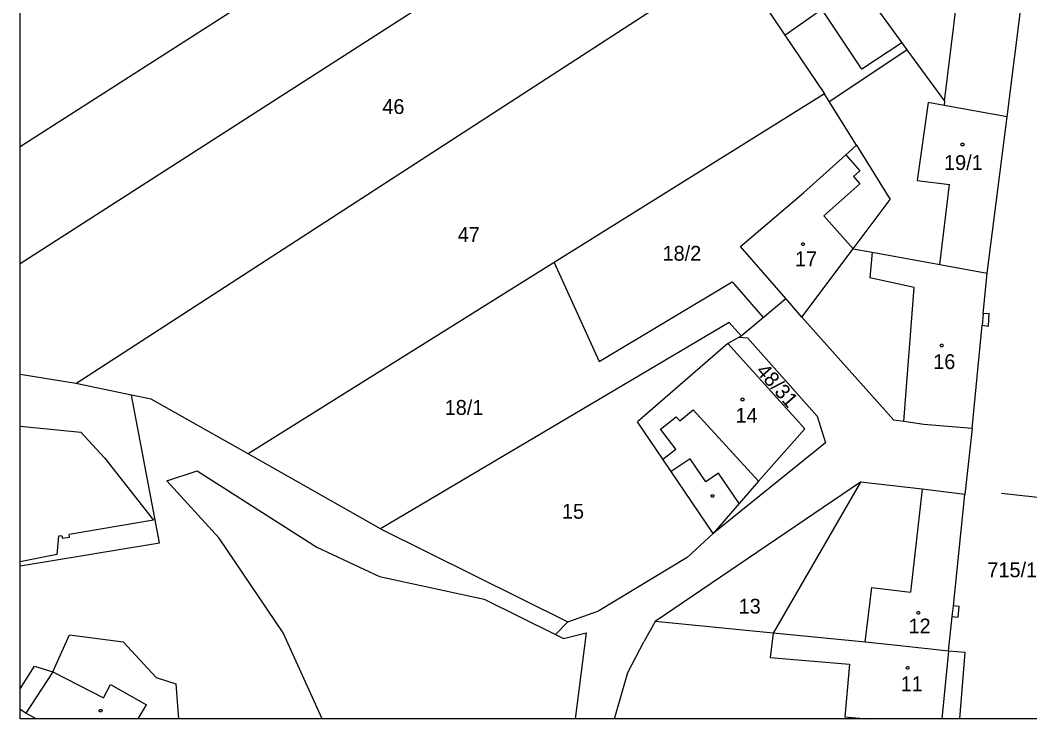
# Model space of a CAD drawing. Extents: x -639621 to -639329, y -1192893 to -1192488.
# Drawn here: x -639621.3 to -639505.7, y -1192893.3 to -1192813.4 of the extents above; entities that cross this region are included whole.
import ezdxf

# ---------------------------------------------------------------- set-up
doc = ezdxf.new("R2010")
doc.units = 0
for name, color, linetype in [('Vrstva 1', 7, 'Continuous'), ('Vrstva 2', 7, 'Continuous'), ('Vrstva 25', 7, 'Continuous'), ('Vrstva 4', 7, 'Continuous'), ('Vrstva 5', 7, 'Continuous'), ('Vrstva 61', 7, 'Continuous')]:
    doc.layers.add(name, color=color, linetype=linetype)

msp = doc.modelspace()

# ---------------------------------------------------------------- linework, layer by layer
at = {"layer": 'Vrstva 1'}
for p, q in [((-639544.66, -1192778.72), (-639621.26, -1192827.88)), ((-639621.26, -1192841.23), (-639539.3, -1192788.57)), ((-639531.35, -1192800.82), (-639520.33, -1192815.94)), ((-639508.25, -1192824.43), (-639505.7, -1192803.94)), ((-639614.88, -1192854.94), (-639539.7, -1192806.21)), ((-639539.7, -1192806.21), (-639533.72, -1192815.06)), ((-639533.72, -1192815.06), (-639529.19, -1192821.78)), ((-639520.33, -1192815.94), (-639519.74, -1192816.75)), ((-639528.63, -1192822.67), (-639519.74, -1192816.75)), ((-639519.74, -1192816.75), (-639515.43, -1192822.65)), ((-639529.19, -1192821.78), (-639560.12, -1192841.09)), ((-639528.63, -1192822.67), (-639529.19, -1192821.78)), ((-639525.5, -1192827.68), (-639528.63, -1192822.67)), ((-639515.43, -1192822.65), (-639515.49, -1192823.12)), ((-639508.25, -1192824.43), (-639515.49, -1192823.12)), ((-639510.56, -1192842.33), (-639508.25, -1192824.43)), ((-639526.73, -1192828.78), (-639525.5, -1192827.68)), ((-639525.5, -1192827.68), (-639521.67, -1192833.89)), ((-639531.59, -1192833.11), (-639526.73, -1192828.78)), ((-639538.8, -1192839.27), (-639531.59, -1192833.11)), ((-639525.91, -1192839.52), (-639521.67, -1192833.89)), ((-639533.62, -1192845.24), (-639538.8, -1192839.27)), ((-639531.79, -1192847.35), (-639525.91, -1192839.52)), ((-639525.91, -1192839.52), (-639523.71, -1192839.92)), ((-639523.71, -1192839.92), (-639515.97, -1192841.34)), ((-639560.12, -1192841.09), (-639595.18, -1192863)), ((-639560.12, -1192841.09), (-639554.98, -1192852.45)), ((-639515.97, -1192841.34), (-639510.56, -1192842.33)), ((-639511.01, -1192846.96), (-639510.56, -1192842.33)), ((-639554.98, -1192852.45), (-639539.77, -1192843.3)), ((-639539.77, -1192843.3), (-639536.21, -1192847.4)), ((-639536.21, -1192847.4), (-639533.62, -1192845.24)), ((-639531.79, -1192847.35), (-639533.62, -1192845.24)), ((-639510.32, -1192846.92), (-639511.01, -1192846.96)), ((-639510.42, -1192848.39), (-639510.32, -1192846.92)), ((-639540.09, -1192847.96), (-639580, -1192871.57)), ((-639538.71, -1192849.49), (-639540.09, -1192847.96)), ((-639538.71, -1192849.49), (-639536.21, -1192847.4)), ((-639521.25, -1192859.13), (-639531.79, -1192847.35)), ((-639512.29, -1192860.12), (-639511.14, -1192848.29)), ((-639511.14, -1192848.29), (-639510.42, -1192848.39)), ((-639540.23, -1192850.37), (-639550.59, -1192859.35)), ((-639540.23, -1192850.37), (-639538.98, -1192849.64)), ((-639531.42, -1192860.16), (-639540.23, -1192850.37)), ((-639538.98, -1192849.64), (-639538.71, -1192849.49)), ((-639538.98, -1192849.64), (-639538.01, -1192849.73)), ((-639538.01, -1192849.73), (-639530.02, -1192858.69)), ((-639614.88, -1192854.94), (-639621.26, -1192853.92)), ((-639608.52, -1192856.27), (-639614.88, -1192854.94)), ((-639605.31, -1192873.2), (-639608.52, -1192856.27)), ((-639606.26, -1192856.74), (-639608.52, -1192856.27)), ((-639595.18, -1192863), (-639606.26, -1192856.74)), ((-639530.02, -1192858.69), (-639529.06, -1192861.73)), ((-639621.26, -1192859.82), (-639614.31, -1192860.51)), ((-639547.69, -1192863.63), (-639550.59, -1192859.35)), ((-639520.08, -1192859.32), (-639521.25, -1192859.13)), ((-639517.82, -1192859.63), (-639520.08, -1192859.32)), ((-639512.29, -1192860.12), (-639517.82, -1192859.63)), ((-639614.31, -1192860.51), (-639611.62, -1192863.46)), ((-639531.42, -1192860.16), (-639536.75, -1192866.15)), ((-639512.29, -1192860.12), (-639513.1, -1192867.65)), ((-639529.06, -1192861.73), (-639541.93, -1192872.12)), ((-639580, -1192871.57), (-639595.18, -1192863)), ((-639611.62, -1192863.46), (-639606, -1192870.58)), ((-639546.73, -1192865.04), (-639547.69, -1192863.63)), ((-639604.47, -1192866.09), (-639601, -1192864.96)), ((-639601, -1192864.96), (-639587.31, -1192873.7)), ((-639541.93, -1192872.12), (-639546.73, -1192865.04)), ((-639598.5, -1192872.64), (-639604.47, -1192866.09)), ((-639525.06, -1192866.23), (-639548.56, -1192882.19)), ((-639536.75, -1192866.15), (-639538.95, -1192868.69)), ((-639525.06, -1192866.23), (-639535.07, -1192883.53)), ((-639517.99, -1192867.05), (-639525.06, -1192866.23)), ((-639513.1, -1192867.65), (-639517.99, -1192867.05)), ((-639514.43, -1192880.41), (-639513.1, -1192867.65)), ((-639538.95, -1192868.69), (-639541.93, -1192872.12)), ((-639606, -1192870.58), (-639615.65, -1192872.22)), ((-639616.87, -1192872.43), (-639617.06, -1192874.51)), ((-639616.49, -1192872.37), (-639616.87, -1192872.43)), ((-639616.49, -1192872.37), (-639616.43, -1192872.67)), ((-639616.43, -1192872.67), (-639615.6, -1192872.53)), ((-639615.6, -1192872.53), (-639615.65, -1192872.22)), ((-639580, -1192871.57), (-639558.56, -1192882.23)), ((-639541.93, -1192872.12), (-639544.9, -1192874.86)), ((-639621.26, -1192875.84), (-639605.31, -1192873.2)), ((-639591.17, -1192883.51), (-639598.5, -1192872.64)), ((-639587.31, -1192873.7), (-639580.13, -1192877.06)), ((-639617.06, -1192874.51), (-639621.26, -1192875.37)), ((-639544.9, -1192874.86), (-639555, -1192880.97)), ((-639580.13, -1192877.06), (-639568.16, -1192879.64)), ((-639568.16, -1192879.64), (-639559.97, -1192883.7)), ((-639513.76, -1192880.48), (-639514.43, -1192880.41)), ((-639513.89, -1192881.71), (-639513.76, -1192880.48)), ((-639558.56, -1192882.23), (-639555, -1192880.97)), ((-639514.97, -1192885.59), (-639514.56, -1192881.64)), ((-639514.56, -1192881.64), (-639513.89, -1192881.71)), ((-639559.97, -1192883.7), (-639558.56, -1192882.23)), ((-639548.56, -1192882.19), (-639549.88, -1192884.53)), ((-639535.07, -1192883.53), (-639548.56, -1192882.19)), ((-639617.51, -1192887.95), (-639615.62, -1192883.72)), ((-639615.62, -1192883.72), (-639609.46, -1192884.51)), ((-639586.7, -1192893.33), (-639591.17, -1192883.51)), ((-639559.97, -1192883.7), (-639559.07, -1192884.15)), ((-639559.07, -1192884.15), (-639556.45, -1192883.48)), ((-639556.45, -1192883.48), (-639557.71, -1192893.33)), ((-639526.07, -1192884.42), (-639535.07, -1192883.53)), ((-639609.46, -1192884.51), (-639605.69, -1192888.6)), ((-639551.68, -1192888.03), (-639549.88, -1192884.53)), ((-639524.51, -1192884.57), (-639526.07, -1192884.42)), ((-639520.5, -1192884.97), (-639524.51, -1192884.57)), ((-639514.97, -1192885.59), (-639520.5, -1192884.97)), ((-639513.07, -1192885.76), (-639514.97, -1192885.59)), ((-639513.7, -1192893.33), (-639513.07, -1192885.76)), ((-639621.26, -1192889.92), (-639619.64, -1192887.29)), ((-639619.64, -1192887.29), (-639617.51, -1192887.95)), ((-639605.69, -1192888.6), (-639603.44, -1192889.34)), ((-639553.21, -1192893.33), (-639551.68, -1192888.03)), ((-639603.44, -1192889.34), (-639603.13, -1192893.33)), ((-639620.61, -1192892.68), (-639621.26, -1192892.26)), ((-639619.43, -1192893.33), (-639620.61, -1192892.68))]:
    msp.add_line(p, q, dxfattribs=at)
at = {"layer": 'Vrstva 25'}
msp.add_line((-639508.9, -1192867.52), (-639502.29, -1192868.24), dxfattribs=at)
at = {"layer": 'Vrstva 4'}
for p, q in [((-639515.43, -1192822.65), (-639514, -1192810.86)), ((-639533.72, -1192815.06), (-639529.47, -1192812.12)), ((-639524.92, -1192818.97), (-639529.47, -1192812.12)), ((-639520.33, -1192815.94), (-639524.92, -1192818.97)), ((-639517.33, -1192822.78), (-639518.57, -1192831.73)), ((-639515.49, -1192823.12), (-639517.33, -1192822.78)), ((-639526.73, -1192828.78), (-639525.12, -1192830.59)), ((-639525.12, -1192830.59), (-639525.87, -1192831.25)), ((-639525.13, -1192832.09), (-639529.25, -1192835.75)), ((-639525.87, -1192831.25), (-639525.13, -1192832.09)), ((-639518.57, -1192831.73), (-639514.87, -1192832.18)), ((-639515.97, -1192841.34), (-639514.87, -1192832.18)), ((-639525.91, -1192839.52), (-639529.25, -1192835.75)), ((-639523.71, -1192839.92), (-639523.99, -1192842.86)), ((-639518.91, -1192843.98), (-639523.99, -1192842.86)), ((-639520.08, -1192859.32), (-639518.91, -1192843.98)), ((-639511.01, -1192846.96), (-639511.14, -1192848.29)), ((-639545.73, -1192859.23), (-639544.2, -1192857.96)), ((-639536.75, -1192866.15), (-639544.2, -1192857.96)), ((-639547.96, -1192860.18), (-639546.15, -1192858.77)), ((-639546.15, -1192858.77), (-639545.73, -1192859.23)), ((-639546.19, -1192862.47), (-639547.96, -1192860.18)), ((-639547.69, -1192863.63), (-639546.19, -1192862.47)), ((-639544.56, -1192863.57), (-639546.73, -1192865.04)), ((-639542.78, -1192866.2), (-639544.56, -1192863.57)), ((-639541.32, -1192865.21), (-639542.78, -1192866.2)), ((-639538.95, -1192868.69), (-639541.32, -1192865.21)), ((-639517.99, -1192867.05), (-639519.35, -1192878.82)), ((-639524.51, -1192884.57), (-639523.78, -1192878.31)), ((-639523.78, -1192878.31), (-639519.35, -1192878.82)), ((-639514.56, -1192881.64), (-639514.43, -1192880.41)), ((-639535.07, -1192883.53), (-639535.39, -1192886.3)), ((-639535.39, -1192886.3), (-639526.32, -1192887.09)), ((-639514.97, -1192885.59), (-639515.73, -1192893.33)), ((-639526.32, -1192887.09), (-639526.87, -1192893.1)), ((-639617.51, -1192887.95), (-639620.61, -1192892.68)), ((-639617.51, -1192887.95), (-639611.74, -1192890.94)), ((-639611.74, -1192890.94), (-639610.92, -1192889.4)), ((-639610.92, -1192889.4), (-639606.79, -1192891.74)), ((-639607.74, -1192893.33), (-639606.79, -1192891.74)), ((-639526.87, -1192893.1), (-639524.3, -1192893.33))]:
    msp.add_line(p, q, dxfattribs=at)
at = {"layer": 'Vrstva 5'}
for points in [[(-639513.29, -1192827.46), (-639513.2, -1192827.61), (-639513.29, -1192827.76), (-639513.47, -1192827.76), (-639513.56, -1192827.61), (-639513.47, -1192827.46)], [(-639531.55, -1192838.84), (-639531.46, -1192838.99), (-639531.55, -1192839.14), (-639531.73, -1192839.14), (-639531.82, -1192838.99), (-639531.73, -1192838.84)], [(-639515.68, -1192850.45), (-639515.59, -1192850.6), (-639515.68, -1192850.75), (-639515.86, -1192850.75), (-639515.95, -1192850.6), (-639515.86, -1192850.45)], [(-639538.48, -1192856.64), (-639538.39, -1192856.79), (-639538.48, -1192856.94), (-639538.66, -1192856.94), (-639538.75, -1192856.79), (-639538.66, -1192856.64)], [(-639541.91, -1192867.68), (-639541.82, -1192867.83), (-639541.91, -1192867.98), (-639542.09, -1192867.98), (-639542.18, -1192867.83), (-639542.09, -1192867.68)], [(-639518.35, -1192881.04), (-639518.26, -1192881.19), (-639518.35, -1192881.34), (-639518.53, -1192881.34), (-639518.62, -1192881.19), (-639518.53, -1192881.04)], [(-639519.57, -1192887.35), (-639519.48, -1192887.5), (-639519.57, -1192887.65), (-639519.75, -1192887.65), (-639519.84, -1192887.5), (-639519.75, -1192887.35)], [(-639611.97, -1192892.25), (-639611.88, -1192892.4), (-639611.97, -1192892.55), (-639612.15, -1192892.55), (-639612.24, -1192892.4), (-639612.15, -1192892.25)]]:
    msp.add_lwpolyline(points, close=True, dxfattribs=at)
at = {"layer": 'Vrstva 61'}
for points in [[(-639621.26, -1192893.33), (-639621.26, -1192487.83)], [(-639329.26, -1192893.33), (-639621.26, -1192893.33)]]:
    msp.add_lwpolyline(points, dxfattribs=at)

# ---------------------------------------------------------------- texts
at = {"layer": 'Vrstva 2'}
for s, p in [('46', (-639579.8, -1192824.1)), ('19/1', (-639515.49, -1192830.51)), ('47', (-639571.17, -1192838.75)), ('18/2', (-639547.72, -1192840.9)), ('17', (-639532.56, -1192841.53)), ('16', (-639516.73, -1192853.3)), ('18/1', (-639572.66, -1192858.54)), ('14', (-639539.37, -1192859.44)), ('15', (-639559.24, -1192870.43)), ('715/1', (-639510.53, -1192877.13)), ('13', (-639539.01, -1192881.29)), ('12', (-639519.56, -1192883.56)), ('11', (-639520.46, -1192890.17))]:
    msp.add_text(s, height=1.7, dxfattribs=at).set_placement(p)
msp.add_text('48/31', height=1.7, rotation=311.6317, dxfattribs=at).set_placement((-639537.11, -1192853.6))

doc.saveas('drawing.dxf')
